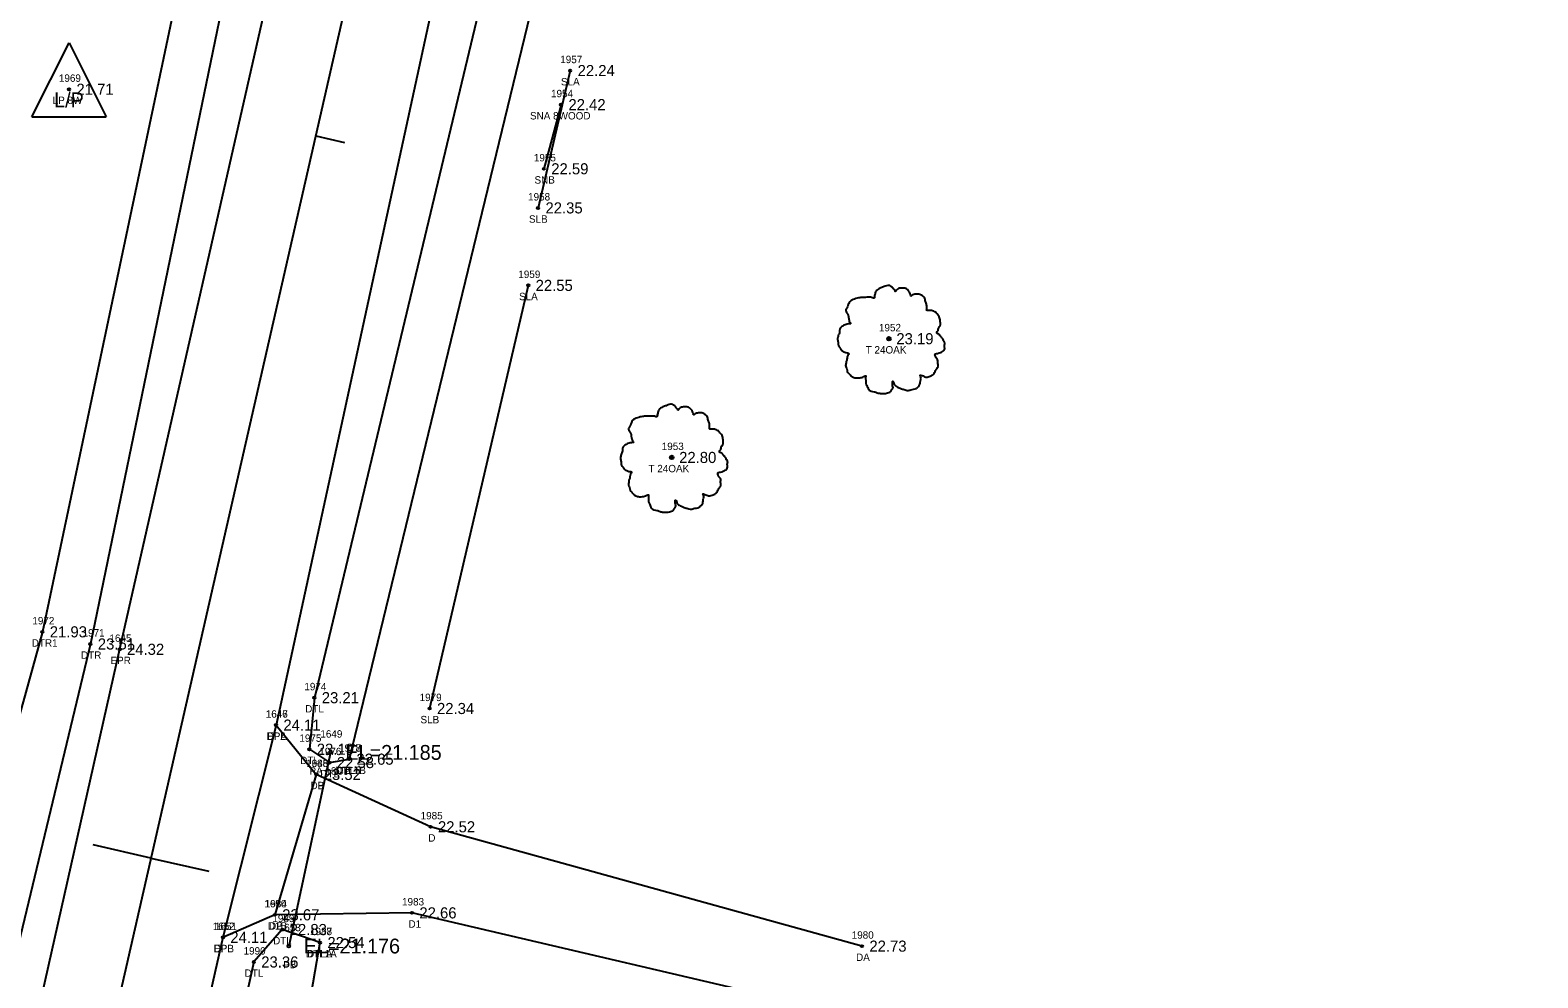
# Model space of a CAD drawing. Extents: x 2654414 to 2656963, y 761776 to 764965.
# Drawn here: x 2655506 to 2655709.5, y 762380.7 to 762508.6 of the extents above; entities that cross this region are included whole.
import ezdxf

# ---------------------------------------------------------------- set-up
doc = ezdxf.new("R2010")
doc.units = 0
for name, color, linetype in [('Default', 7, 'Continuous'), ('RD_EX_BldgApp', 7, 'Continuous'), ('RD_EX_BldgApp_txCode', 7, 'Continuous'), ('RD_EX_DR_Pipe', 7, 'Continuous'), ('RD_EX_DR_Pipe_txCode', 7, 'Continuous'), ('RD_EX_Driveway', 7, 'Continuous'), ('RD_EX_Driveway_txCode', 7, 'Continuous'), ('RD_EX_H2O', 7, 'Continuous'), ('RD_EX_H2O_txCode', 7, 'Continuous'), ('RD_EX_Road', 7, 'Continuous'), ('RD_EX_Road_txCode', 7, 'Continuous'), ('RD_EX_TX_BldgApp_ELEV', 7, 'Continuous'), ('RD_EX_TX_Driveway_ELEV', 7, 'Continuous'), ('RD_EX_TX_H2O_ELEV', 7, 'Continuous'), ('RD_EX_TX_Road_ELEV', 7, 'Continuous'), ('RD_EX_TX_UT_ELEV', 7, 'Continuous'), ('RD_EX_TX_VEG_ELEV', 7, 'Continuous'), ('RD_EX_UT', 7, 'Continuous'), ('RD_EX_UT_txCode', 7, 'Continuous'), ('RD_EX_VEG', 7, 'Continuous'), ('RD_EX_VEG_txCode', 7, 'Continuous'), ('RD_HC_Cl', 7, 'Continuous'), ('RD_HC_Data_Tic', 7, 'Continuous'), ('RD_SMD_Locator', 7, 'Continuous'), ('RD_TX_Pipe_ElevEX', 7, 'Continuous')]:
    doc.layers.add(name, color=color, linetype=linetype)

msp = doc.modelspace()

# ---------------------------------------------------------------- linework, layer by layer
at = {"layer": 'Default'}
msp.add_line((2656050.51, 764712.37), (2655383.26, 761787.51), dxfattribs=at)
at = {"layer": 'RD_EX_BldgApp'}
msp.add_line((2655577.64, 762498.57), (2655575.32, 762489.91), dxfattribs=at)
at = {"layer": 'RD_EX_DR_Pipe'}
msp.add_line((2655546.51, 762411.12), (2655540.89, 762384.98), dxfattribs=at)
at = {"layer": 'RD_EX_Driveway'}
for points in [[(2655539.15, 762414.81), (2655544.59, 762408.15), (2655538.99, 762389.2), (2655531.98, 762386.15)], [(2655618.28, 762384.97), (2655560.02, 762401.08), (2655544.59, 762408.15)], [(2655615.95, 762375.77), (2655557.51, 762389.46), (2655538.99, 762389.2)]]:
    msp.add_lwpolyline(points, dxfattribs=at)
at = {"layer": 'RD_EX_H2O'}
msp.add_line((2655545.09, 762385.45), (2655536.84, 762338.21), dxfattribs=at)
for points in [[(2655587.51, 762572.52), (2655582.24, 762574.09), (2655567.43, 762515.07), (2655544.33, 762418.51), (2655543.66, 762411.55), (2655546.37, 762409.75), (2655549.01, 762410.21)], [(2655587.51, 762572.52), (2655573.85, 762512.33), (2655549.01, 762410.21)], [(2655543.55, 762560.68), (2655539.34, 762565), (2655535.47, 762561.26), (2655533.61, 762546.63), (2655528.16, 762524.75), (2655507.6, 762427.4), (2655486.29, 762350.37), (2655477.51, 762339.55)], [(2655543.55, 762560.68), (2655534.37, 762523.92), (2655514.09, 762425.76), (2655491.38, 762331.28), (2655488.62, 762321.94), (2655478.48, 762315.45), (2655472.03, 762316.1)], [(2655545.09, 762385.45), (2655540, 762387.21), (2655536.16, 762382.83), (2655523.31, 762324.66), (2655511.9, 762277.49)]]:
    msp.add_lwpolyline(points, dxfattribs=at)
at = {"layer": 'RD_EX_Road'}
for points in [[(2655700.99, 763232.28), (2655693.55, 763198.57), (2655671.65, 763102.04), (2655649.04, 763001.06), (2655627.27, 762906.23), (2655605, 762809.37), (2655598.99, 762783.09), (2655583.65, 762714.14), (2655561.97, 762618.32), (2655556.36, 762593.84), (2655548.11, 762557.14), (2655540.1, 762522.48), (2655518.03, 762425.04), (2655496.48, 762329.56), (2655475.55, 762236.62), (2655473.2, 762226.14), (2655466.57, 762197.5), (2655460.06, 762168.16), (2655454.26, 762143.78), (2655432.5, 762049.88), (2655410.7, 761955.51), (2655388.17, 761858.43), (2655373.5, 761793.95)], [(2655670.04, 762995.18), (2655648.57, 762900.67), (2655631.27, 762824.03), (2655626.67, 762802.87), (2655621.78, 762781.91), (2655611.71, 762738.43), (2655604.93, 762708.62), (2655582.64, 762610.54), (2655576.46, 762583.32), (2655561.41, 762517.24), (2655539.15, 762414.81), (2655531.98, 762386.15), (2655517.98, 762324.29), (2655508.17, 762280.15), (2655501.46, 762251.6), (2655496.92, 762232.09), (2655477.2, 762144.97), (2655472.14, 762122.52), (2655453.74, 762045.1), (2655431.79, 761949.92), (2655409.76, 761853.25), (2655401.25, 761816.42), (2655394.61, 761787.37)]]:
    msp.add_lwpolyline(points, dxfattribs=at)
at = {"layer": 'RD_EX_UT'}
for p, q in [((2655506.2, 762496.92), (2655511.2, 762506.92)), ((2655511.2, 762506.92), (2655516.2, 762496.92)), ((2655506.2, 762496.92), (2655516.2, 762496.92))]:
    msp.add_line(p, q, dxfattribs=at)
at = {"layer": 'RD_EX_VEG'}
for p, q in [((2655578.88, 762503.17), (2655574.54, 762484.63)), ((2655573.21, 762474.17), (2655559.89, 762417.05))]:
    msp.add_line(p, q, dxfattribs=at)
for centre, radius in [((2655621.92, 762466.97), 0.25), ((2655621.9, 762466.95), 0.0001), ((2655592.59, 762450.94), 0.25), ((2655592.57, 762450.92), 0.0001)]:
    msp.add_circle(centre, radius, dxfattribs=at)
for points in [[(2655622.05, 762474.14), (2655621.75, 762474.16), (2655621.42, 762474.06), (2655621.17, 762473.96), (2655620.95, 762473.89), (2655620.72, 762473.79), (2655620.42, 762473.61), (2655620.2, 762473.41), (2655620.07, 762473.16), (2655620.02, 762472.94), (2655619.97, 762472.66), (2655619.97, 762472.49), (2655619.85, 762472.46), (2655619.7, 762472.49), (2655619.45, 762472.56), (2655619.2, 762472.56), (2655618.95, 762472.56), (2655618.6, 762472.54), (2655618.25, 762472.54), (2655617.98, 762472.49), (2655617.65, 762472.44), (2655617.28, 762472.31), (2655616.93, 762472.19), (2655616.63, 762471.94), (2655616.38, 762471.46), (2655616.25, 762471.11), (2655616.1, 762470.86), (2655616.25, 762470.41), (2655616.43, 762470.06), (2655616.45, 762469.86), (2655616.53, 762469.44), (2655616.63, 762469.21), (2655616.75, 762469.01), (2655616.68, 762468.99), (2655616.3, 762468.94), (2655616, 762468.84), (2655615.58, 762468.61), (2655615.35, 762468.39), (2655615.25, 762468.07), (2655615.23, 762467.72), (2655615.13, 762467.52), (2655615.05, 762467.24), (2655615.03, 762467.17), (2655614.98, 762466.84), (2655615.08, 762466.39), (2655615.1, 762466.04), (2655615.23, 762465.82), (2655615.38, 762465.64), (2655615.55, 762465.39), (2655615.95, 762465.17), (2655616.28, 762465.07), (2655616.48, 762465.04), (2655616.3, 762464.54), (2655616.25, 762464.19), (2655616.13, 762463.79), (2655616.13, 762463.72), (2655616.08, 762463.24), (2655616.23, 762462.92), (2655616.3, 762462.54), (2655616.48, 762462.32), (2655616.75, 762462.02), (2655617.08, 762461.79), (2655617.58, 762461.67), (2655617.98, 762461.69), (2655618.55, 762461.87), (2655618.8, 762461.94), (2655618.77, 762461.77), (2655618.8, 762461.39), (2655618.8, 762460.97), (2655618.95, 762460.64), (2655619.05, 762460.37), (2655619.2, 762460.12), (2655619.52, 762459.89), (2655619.92, 762459.82), (2655620.35, 762459.67), (2655620.8, 762459.59), (2655621.3, 762459.57), (2655621.9, 762459.72), (2655622.17, 762459.84), (2655622.27, 762460.02), (2655622.47, 762460.39), (2655622.42, 762460.62), (2655622.45, 762461.22), (2655622.55, 762461.04), (2655622.72, 762460.69), (2655623.22, 762460.39), (2655623.62, 762460.22), (2655624.1, 762460.07), (2655624.4, 762459.99), (2655624.87, 762460.07), (2655625.25, 762460.14), (2655625.62, 762460.27), (2655625.92, 762460.54), (2655626.1, 762460.82), (2655626.15, 762461.09), (2655626.22, 762461.47), (2655626.27, 762461.64)], [(2655626.27, 762461.64), (2655626.2, 762461.82), (2655626.15, 762462.07), (2655626.22, 762462.04), (2655626.4, 762461.99), (2655626.67, 762461.87), (2655626.9, 762461.79), (2655627.22, 762461.82), (2655627.5, 762461.92), (2655627.95, 762462.19), (2655628.22, 762462.67), (2655628.5, 762463.07), (2655628.57, 762463.39), (2655628.52, 762463.62), (2655628.5, 762464.12), (2655628.3, 762464.37), (2655628.25, 762464.49), (2655628.15, 762464.89), (2655628.22, 762464.94), (2655628.5, 762464.99), (2655628.87, 762465.12), (2655629.15, 762465.24), (2655629.37, 762465.42), (2655629.45, 762465.64), (2655629.42, 762466.04), (2655629.47, 762466.44), (2655629.4, 762466.59), (2655629.3, 762466.74), (2655629.22, 762466.94), (2655629.07, 762467.09), (2655628.97, 762467.24), (2655628.87, 762467.34), (2655628.75, 762467.49), (2655628.57, 762467.62), (2655628.42, 762467.67), (2655628.37, 762467.82), (2655628.52, 762468.02), (2655628.57, 762468.12), (2655628.6, 762468.34), (2655628.82, 762468.69), (2655628.87, 762469.09), (2655628.82, 762469.51), (2655628.77, 762469.79), (2655628.62, 762470.06), (2655628.42, 762470.31), (2655628.3, 762470.49), (2655628.12, 762470.61), (2655627.8, 762470.74), (2655627.55, 762470.79), (2655627.2, 762470.79), (2655627, 762470.84), (2655627.02, 762470.89), (2655627.02, 762471.04), (2655627.02, 762471.31), (2655626.95, 762471.76), (2655626.8, 762472.26), (2655626.8, 762472.29), (2655626.7, 762472.54), (2655626.47, 762472.74), (2655626.3, 762472.84), (2655626.1, 762472.96), (2655625.85, 762472.99), (2655625.55, 762472.99), (2655625.27, 762472.94), (2655625.07, 762472.84), (2655624.9, 762472.71), (2655624.82, 762472.86), (2655624.72, 762473.16), (2655624.67, 762473.31), (2655624.52, 762473.49), (2655624.3, 762473.69), (2655623.85, 762473.81), (2655623.22, 762473.74), (2655622.92, 762473.54), (2655622.77, 762473.36), (2655622.72, 762473.49), (2655622.52, 762473.69), (2655622.42, 762473.86), (2655622.25, 762473.99), (2655622.1, 762474.09), (2655622, 762474.14)], [(2655592.72, 762458.11), (2655592.42, 762458.13), (2655592.09, 762458.03), (2655591.84, 762457.93), (2655591.62, 762457.86), (2655591.39, 762457.76), (2655591.09, 762457.58), (2655590.87, 762457.38), (2655590.74, 762457.13), (2655590.69, 762456.91), (2655590.64, 762456.63), (2655590.64, 762456.46), (2655590.52, 762456.43), (2655590.37, 762456.46), (2655590.12, 762456.53), (2655589.87, 762456.53), (2655589.62, 762456.53), (2655589.27, 762456.51), (2655588.92, 762456.51), (2655588.64, 762456.46), (2655588.32, 762456.41), (2655587.95, 762456.28), (2655587.6, 762456.16), (2655587.3, 762455.91), (2655587.05, 762455.43), (2655586.92, 762455.08), (2655586.77, 762454.83), (2655586.92, 762454.38), (2655587.1, 762454.03), (2655587.12, 762453.83), (2655587.2, 762453.41), (2655587.3, 762453.18), (2655587.42, 762452.98), (2655587.35, 762452.96), (2655586.97, 762452.91), (2655586.67, 762452.81), (2655586.25, 762452.58), (2655586.02, 762452.36), (2655585.92, 762452.03), (2655585.9, 762451.68), (2655585.8, 762451.48), (2655585.72, 762451.21), (2655585.7, 762451.13), (2655585.65, 762450.81), (2655585.75, 762450.36), (2655585.77, 762450.01), (2655585.9, 762449.78), (2655586.05, 762449.61), (2655586.22, 762449.36), (2655586.62, 762449.13), (2655586.95, 762449.03), (2655587.15, 762449.01), (2655586.97, 762448.51), (2655586.92, 762448.16), (2655586.8, 762447.76), (2655586.8, 762447.68), (2655586.75, 762447.21), (2655586.9, 762446.88), (2655586.97, 762446.51), (2655587.15, 762446.29), (2655587.42, 762445.99), (2655587.75, 762445.76), (2655588.24, 762445.64), (2655588.64, 762445.66), (2655589.22, 762445.84), (2655589.47, 762445.91), (2655589.44, 762445.74), (2655589.47, 762445.36), (2655589.47, 762444.94), (2655589.62, 762444.61), (2655589.72, 762444.34), (2655589.87, 762444.09), (2655590.19, 762443.86), (2655590.59, 762443.79), (2655591.02, 762443.64), (2655591.47, 762443.56), (2655591.97, 762443.54), (2655592.57, 762443.69), (2655592.84, 762443.81), (2655592.94, 762443.99), (2655593.14, 762444.36), (2655593.09, 762444.59), (2655593.12, 762445.19), (2655593.22, 762445.01), (2655593.39, 762444.66), (2655593.89, 762444.36), (2655594.29, 762444.19), (2655594.77, 762444.04), (2655595.07, 762443.96), (2655595.54, 762444.04), (2655595.92, 762444.11), (2655596.29, 762444.24), (2655596.59, 762444.51), (2655596.77, 762444.79), (2655596.82, 762445.06), (2655596.89, 762445.44), (2655596.94, 762445.61)], [(2655596.94, 762445.61), (2655596.87, 762445.79), (2655596.82, 762446.04), (2655596.89, 762446.01), (2655597.07, 762445.96), (2655597.34, 762445.84), (2655597.57, 762445.76), (2655597.89, 762445.79), (2655598.17, 762445.89), (2655598.62, 762446.16), (2655598.89, 762446.64), (2655599.17, 762447.03), (2655599.24, 762447.36), (2655599.19, 762447.58), (2655599.17, 762448.08), (2655598.97, 762448.33), (2655598.92, 762448.46), (2655598.82, 762448.86), (2655598.89, 762448.91), (2655599.17, 762448.96), (2655599.54, 762449.08), (2655599.81, 762449.21), (2655600.04, 762449.38), (2655600.11, 762449.61), (2655600.09, 762450.01), (2655600.14, 762450.41), (2655600.06, 762450.56), (2655599.96, 762450.71), (2655599.89, 762450.91), (2655599.74, 762451.06), (2655599.64, 762451.21), (2655599.54, 762451.31), (2655599.42, 762451.46), (2655599.24, 762451.58), (2655599.09, 762451.63), (2655599.04, 762451.78), (2655599.19, 762451.98), (2655599.24, 762452.08), (2655599.27, 762452.31), (2655599.49, 762452.66), (2655599.54, 762453.06), (2655599.49, 762453.48), (2655599.44, 762453.76), (2655599.29, 762454.03), (2655599.09, 762454.28), (2655598.97, 762454.46), (2655598.79, 762454.58), (2655598.47, 762454.71), (2655598.22, 762454.76), (2655597.87, 762454.76), (2655597.67, 762454.81), (2655597.69, 762454.86), (2655597.69, 762455.01), (2655597.69, 762455.28), (2655597.62, 762455.73), (2655597.47, 762456.23), (2655597.47, 762456.26), (2655597.37, 762456.51), (2655597.14, 762456.71), (2655596.97, 762456.81), (2655596.77, 762456.93), (2655596.52, 762456.96), (2655596.22, 762456.96), (2655595.94, 762456.91), (2655595.74, 762456.81), (2655595.57, 762456.68), (2655595.49, 762456.83), (2655595.39, 762457.13), (2655595.34, 762457.28), (2655595.19, 762457.46), (2655594.97, 762457.66), (2655594.52, 762457.78), (2655593.89, 762457.71), (2655593.59, 762457.51), (2655593.44, 762457.33), (2655593.39, 762457.46), (2655593.19, 762457.66), (2655593.09, 762457.83), (2655592.92, 762457.96), (2655592.77, 762458.06), (2655592.67, 762458.11)]]:
    msp.add_spline(points, degree=3, dxfattribs=at)
at = {"layer": 'RD_HC_Cl'}
msp.add_line((2656050.51, 764712.37), (2655383.26, 761787.51), dxfattribs=at)
at = {"layer": 'RD_HC_Data_Tic'}
for p, q in [((2655544.51, 762494.35), (2655548.41, 762493.46)), ((2655522.27, 762396.86), (2655514.47, 762398.64)), ((2655522.27, 762396.86), (2655530.07, 762395.08))]:
    msp.add_line(p, q, dxfattribs=at)
at = {"layer": 'RD_SMD_Locator'}
for centre, radius in [((2655578.88, 762503.17), 0.15), ((2655511.2, 762500.65), 0.15), ((2655577.64, 762498.57), 0.15), ((2655575.32, 762489.91), 0.15), ((2655574.54, 762484.63), 0.15), ((2655573.21, 762474.17), 0.15), ((2655621.92, 762466.97), 0.15), ((2655592.59, 762450.94), 0.15), ((2655507.6, 762427.4), 0.15), ((2655514.09, 762425.76), 0.15), ((2655518.03, 762425.04), 0.15), ((2655544.33, 762418.51), 0.15), ((2655559.89, 762417.05), 0.15), ((2655539.15, 762414.81), 0.15), ((2655539.15, 762414.81), 0.15), ((2655543.66, 762411.55), 0.15), ((2655546.51, 762411.12), 0.2), ((2655549.01, 762410.21), 0.15), ((2655549.01, 762410.21), 0.15), ((2655544.59, 762408.15), 0.15), ((2655544.59, 762408.15), 0.15), ((2655546.37, 762409.75), 0.15), ((2655560.02, 762401.08), 0.15), ((2655557.51, 762389.46), 0.15), ((2655538.99, 762389.2), 0.15), ((2655538.99, 762389.2), 0.15), ((2655531.98, 762386.15), 0.15), ((2655531.98, 762386.15), 0.15), ((2655540, 762387.21), 0.15), ((2655545.09, 762385.45), 0.15), ((2655545.09, 762385.45), 0.15), ((2655540.89, 762384.98), 0.2), ((2655618.28, 762384.97), 0.15), ((2655536.16, 762382.83), 0.15)]:
    msp.add_circle(centre, radius, dxfattribs=at)

# ---------------------------------------------------------------- texts
at = {"layer": 'RD_EX_BldgApp_txCode'}
for s, p in [('1954', (2655576.29, 762499.57)), ('SNA 8WOOD', (2655573.45, 762496.57)), ('1955', (2655573.97, 762490.91)), ('SNB', (2655574.06, 762487.91))]:
    msp.add_text(s, height=1, dxfattribs=at).set_placement(p)
at = {"layer": 'RD_EX_DR_Pipe_txCode'}
for s, p in [('1649', (2655545.14, 762413.12)), ('PA 18CP', (2655543.67, 762408.12)), ('1653', (2655539.52, 762386.98)), ('PB', (2655540.11, 762381.98))]:
    msp.add_text(s, height=1, dxfattribs=at).set_placement(p)
at = {"layer": 'RD_EX_Driveway_txCode'}
for s, p in [('1647', (2655537.78, 762415.81)), ('DPA', (2655537.89, 762412.81)), ('1648', (2655543.22, 762409.15)), ('1986', (2655543.22, 762409.15)), ('DP', (2655543.81, 762406.15)), ('DB', (2655543.81, 762406.15)), ('1985', (2655558.68, 762402.08)), ('D', (2655559.72, 762399.08)), ('1650', (2655537.58, 762390.2)), ('1984', (2655537.64, 762390.2)), ('1983', (2655556.17, 762390.46)), ('1651', (2655530.9, 762387.15)), ('D1B', (2655538.05, 762387.2)), ('DP', (2655538.21, 762387.2)), ('D1', (2655557.04, 762387.46)), ('1980', (2655616.89, 762385.97)), ('DPB', (2655530.73, 762384.15)), ('DA', (2655617.48, 762382.97))]:
    msp.add_text(s, height=1, dxfattribs=at).set_placement(p)
at = {"layer": 'RD_EX_H2O_txCode'}
for s, p in [('1972', (2655506.25, 762428.4)), ('DTR1', (2655506.17, 762425.4)), ('1971', (2655513.03, 762426.76)), ('DTR', (2655512.82, 762423.76)), ('1974', (2655542.98, 762419.51)), ('DTL', (2655543.09, 762416.51)), ('1975', (2655542.31, 762412.55)), ('1977', (2655547.66, 762411.21)), ('1978', (2655547.66, 762411.21)), ('DTL', (2655542.42, 762409.55)), ('1976', (2655545, 762410.75)), ('DTL', (2655545.13, 762407.75)), ('DTL1B', (2655547.13, 762408.21)), ('DTLB', (2655547.29, 762408.21)), ('1989', (2655538.66, 762388.21)), ('DTL', (2655538.76, 762385.21)), ('1987', (2655543.74, 762386.45)), ('1988', (2655543.74, 762386.45)), ('1990', (2655534.77, 762383.83)), ('DTL1A', (2655543.19, 762383.45)), ('DTLA', (2655543.35, 762383.45)), ('DTL', (2655534.91, 762380.83))]:
    msp.add_text(s, height=1, dxfattribs=at).set_placement(p)
at = {"layer": 'RD_EX_Road_txCode'}
for s, p in [('1645', (2655516.66, 762426.04)), ('EPR', (2655516.8, 762423.04)), ('1646', (2655537.76, 762415.81)), ('EPL', (2655537.95, 762412.81)), ('1652', (2655530.61, 762387.15)), ('EPL', (2655530.78, 762384.15))]:
    msp.add_text(s, height=1, dxfattribs=at).set_placement(p)
at = {"layer": 'RD_EX_TX_BldgApp_ELEV'}
for s, p in [('22.42', (2655578.64, 762497.82)), ('22.59', (2655576.32, 762489.16))]:
    msp.add_text(s, height=1.5, dxfattribs=at).set_placement(p)
at = {"layer": 'RD_EX_TX_Driveway_ELEV'}
for s, p in [('24.11', (2655540.15, 762414.06)), ('23.52', (2655545.59, 762407.4)), ('23.52', (2655545.59, 762407.4)), ('22.52', (2655561.02, 762400.33)), ('23.67', (2655539.99, 762388.45)), ('23.67', (2655539.99, 762388.45)), ('22.66', (2655558.51, 762388.71)), ('24.11', (2655532.98, 762385.4)), ('22.73', (2655619.28, 762384.22))]:
    msp.add_text(s, height=1.5, dxfattribs=at).set_placement(p)
at = {"layer": 'RD_EX_TX_H2O_ELEV'}
for s, p in [('21.93', (2655508.6, 762426.65)), ('23.51', (2655515.09, 762425.01)), ('23.21', (2655545.33, 762417.76)), ('23.19', (2655544.66, 762410.8)), ('22.58', (2655547.37, 762409)), ('22.65', (2655550.01, 762409.46)), ('22.65', (2655550.01, 762409.46)), ('22.83', (2655541, 762386.46)), ('22.54', (2655546.09, 762384.7)), ('22.54', (2655546.09, 762384.7)), ('23.36', (2655537.16, 762382.08))]:
    msp.add_text(s, height=1.5, dxfattribs=at).set_placement(p)
at = {"layer": 'RD_EX_TX_Road_ELEV'}
for s, p in [('24.32', (2655519.03, 762424.29)), ('24.11', (2655540.15, 762414.06)), ('24.11', (2655532.98, 762385.4))]:
    msp.add_text(s, height=1.5, dxfattribs=at).set_placement(p)
at = {"layer": 'RD_EX_TX_UT_ELEV'}
msp.add_text('21.71', height=1.5, dxfattribs=at).set_placement((2655512.2, 762499.9))
at = {"layer": 'RD_EX_TX_VEG_ELEV'}
for s, p in [('22.24', (2655579.88, 762502.42)), ('22.35', (2655575.54, 762483.88)), ('22.55', (2655574.21, 762473.42)), ('23.19', (2655622.92, 762466.22)), ('22.80', (2655593.59, 762450.19)), ('22.34', (2655560.89, 762416.3))]:
    msp.add_text(s, height=1.5, dxfattribs=at).set_placement(p)
at = {"layer": 'RD_EX_UT'}
msp.add_text('L/P', height=2, dxfattribs=at).set_placement((2655509.19, 762498.21))
at = {"layer": 'RD_EX_UT_txCode'}
for s, p in [('1969', (2655509.83, 762501.65)), ('LP 8W', (2655508.99, 762498.65))]:
    msp.add_text(s, height=1, dxfattribs=at).set_placement(p)
at = {"layer": 'RD_EX_VEG_txCode'}
for s, p in [('1957', (2655577.53, 762504.17)), ('SLA', (2655577.63, 762501.17)), ('1958', (2655573.19, 762485.63)), ('SLB', (2655573.31, 762482.63)), ('1959', (2655571.87, 762475.17)), ('SLA', (2655571.97, 762472.17)), ('1952', (2655620.57, 762467.97)), ('T 24OAK', (2655618.78, 762464.97)), ('1953', (2655591.24, 762451.94)), ('T 24OAK', (2655589.45, 762448.94)), ('1979', (2655558.54, 762418.05)), ('SLB', (2655558.66, 762415.05))]:
    msp.add_text(s, height=1, dxfattribs=at).set_placement(p)
at = {"layer": 'RD_TX_Pipe_ElevEX'}
for s, p in [('EL=21.185', (2655548.51, 762410.12)), ('EL=21.176', (2655542.89, 762383.98))]:
    msp.add_text(s, height=2, dxfattribs=at).set_placement(p)

doc.saveas('drawing.dxf')
